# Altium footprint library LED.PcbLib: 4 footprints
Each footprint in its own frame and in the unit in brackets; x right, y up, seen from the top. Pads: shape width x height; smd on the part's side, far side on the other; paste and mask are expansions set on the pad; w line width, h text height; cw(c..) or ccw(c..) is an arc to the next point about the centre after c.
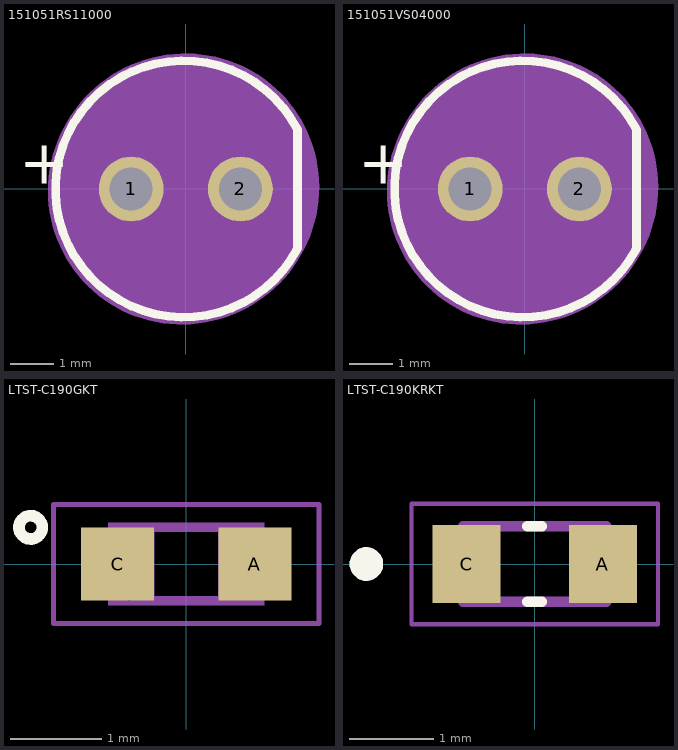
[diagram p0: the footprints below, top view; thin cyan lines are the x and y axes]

## 151051RS11000 [mm] "Red 645nm LED Indication - Discrete 2.1V Radial"
pads (2):
  round 1.508 hole 1: 1(-1.27,0) 2(1.27,0)
Top Overlay:
  lines w0.2: 2.589,-1.401 cw(c-0.047,0) 2.589,1.401 ; 2.6,-1.38 2.6,1.38
  text "+" at -3.88,0.118 h1.02
Mechanical 13:
  circle w0.1: c0,0 r2.5
  lines w0.1: 2.493,-1.452 cw(c-0.021,0) 2.493,1.452 ; 2.5,-1.44 2.5,1.44
  text "+" at -3.887,0.131 h1.02
Mechanical 15:
  region: 0.216,3.141 0.376,3.126 0.534,3.103 0.692,3.071 0.847,3.031 1,2.983 1.151,2.928 1.298,2.865 1.442,2.794 1.582,2.715 1.718,2.63 1.849,2.538 1.975,2.439 2.096,2.334 2.212,2.222 2.321,2.105 2.424,1.982 2.521,1.854 2.611,1.721 2.694,1.584 2.77,1.443 2.838,1.297 2.899,1.149 2.952,0.998 2.997,0.844 3.034,0.688 3.063,0.53 3.083,0.371 3.096,0.211 3.1,0.05 3.096,-0.116 3.083,-0.281 3.061,-0.445 3.032,-0.608 2.993,-0.77 2.947,-0.929 2.892,-1.085 2.829,-1.238 2.759,-1.388 2.681,-1.534 2.595,-1.676 2.502,-1.813 2.402,-1.945 2.295,-2.072 2.182,-2.193 2.063,-2.308 1.938,-2.417 1.808,-2.519 1.672,-2.615 1.532,-2.703 1.387,-2.784 1.239,-2.857 1.087,-2.922 0.931,-2.98 0.773,-3.029 0.613,-3.07 0.45,-3.103 0.286,-3.127 0.121,-3.143 -0.049,-3.15 -0.052,-3.15 -0.211,-3.148 -0.374,-3.138 -0.537,-3.119 -0.699,-3.092 -0.859,-3.056 -1.017,-3.012 -1.173,-2.959 -1.325,-2.898 -1.474,-2.83 -1.619,-2.753 -1.76,-2.669 -1.896,-2.577 -2.027,-2.479 -2.153,-2.374 -2.273,-2.262 -2.387,-2.144 -2.495,-2.02 -2.595,-1.89 -2.689,-1.756 -2.776,-1.616 -2.855,-1.473 -2.926,-1.325 -2.99,-1.174 -3.045,-1.019 -3.092,-0.862 -3.131,-0.703 -3.161,-0.541 -3.183,-0.379 -3.196,-0.215 -3.2,-0.051 -3.196,0.118 -3.182,0.287 -3.16,0.455 -3.129,0.621 -3.089,0.786 -3.04,0.948 -2.983,1.108 -2.917,1.264 -2.844,1.416 -2.762,1.565 -2.673,1.709 -2.576,1.848 -2.472,1.981 -2.361,2.109 -2.243,2.231 -2.119,2.347 -1.989,2.455 -1.854,2.557 -1.713,2.652 -1.568,2.739 -1.418,2.818 -1.264,2.889 -1.107,2.951 -0.946,3.006 -0.783,3.051 -0.618,3.089 -0.451,3.117 -0.283,3.136 -0.114,3.147 0.051,3.148
3D body "Download_STP_WL-TMRC-5mm+(rev1).stp": height 8.7, standoff -26.4, extent -2.954,-3.048 2.446,2.832

## 151051VS04000 [mm] "Green 572nm LED Indication - Discrete 2.1V Radial"
pads (2):
  round 1.508 hole 1: 1(-1.27,0) 2(1.27,0)
Top Overlay:
  lines w0.2: 2.589,-1.401 cw(c-0.047,0) 2.589,1.401 ; 2.6,-1.38 2.6,1.38
  text "+" at -3.88,0.118 h1.02
Mechanical 13:
  circle w0.1: c0,0 r2.5
  lines w0.1: 2.493,-1.452 cw(c-0.021,0) 2.493,1.452 ; 2.5,-1.44 2.5,1.44
  text "+" at -3.887,0.131 h1.02
Mechanical 15:
  region: 0.216,3.141 0.376,3.126 0.534,3.103 0.692,3.071 0.847,3.031 1,2.983 1.151,2.928 1.298,2.865 1.442,2.794 1.582,2.715 1.718,2.63 1.849,2.538 1.975,2.439 2.096,2.334 2.212,2.222 2.321,2.105 2.424,1.982 2.521,1.854 2.611,1.721 2.694,1.584 2.77,1.443 2.838,1.297 2.899,1.149 2.952,0.998 2.997,0.844 3.034,0.688 3.063,0.53 3.083,0.371 3.096,0.211 3.1,0.05 3.096,-0.116 3.083,-0.281 3.061,-0.445 3.032,-0.608 2.993,-0.77 2.947,-0.929 2.892,-1.085 2.829,-1.238 2.759,-1.388 2.681,-1.534 2.595,-1.676 2.502,-1.813 2.402,-1.945 2.295,-2.072 2.182,-2.193 2.063,-2.308 1.938,-2.417 1.808,-2.519 1.672,-2.615 1.532,-2.703 1.387,-2.784 1.239,-2.857 1.087,-2.922 0.931,-2.98 0.773,-3.029 0.613,-3.07 0.45,-3.103 0.286,-3.127 0.121,-3.143 -0.049,-3.15 -0.052,-3.15 -0.211,-3.148 -0.374,-3.138 -0.537,-3.119 -0.699,-3.092 -0.859,-3.056 -1.017,-3.012 -1.173,-2.959 -1.325,-2.898 -1.474,-2.83 -1.619,-2.753 -1.76,-2.669 -1.896,-2.577 -2.027,-2.479 -2.153,-2.374 -2.273,-2.262 -2.387,-2.144 -2.495,-2.02 -2.595,-1.89 -2.689,-1.756 -2.776,-1.616 -2.855,-1.473 -2.926,-1.325 -2.99,-1.174 -3.045,-1.019 -3.092,-0.862 -3.131,-0.703 -3.161,-0.541 -3.183,-0.379 -3.196,-0.215 -3.2,-0.051 -3.196,0.118 -3.182,0.287 -3.16,0.455 -3.129,0.621 -3.089,0.786 -3.04,0.948 -2.983,1.108 -2.917,1.264 -2.844,1.416 -2.762,1.565 -2.673,1.709 -2.576,1.848 -2.472,1.981 -2.361,2.109 -2.243,2.231 -2.119,2.347 -1.989,2.455 -1.854,2.557 -1.713,2.652 -1.568,2.739 -1.418,2.818 -1.264,2.889 -1.107,2.951 -0.946,3.006 -0.783,3.051 -0.618,3.089 -0.451,3.117 -0.283,3.136 -0.114,3.147 0.051,3.148
3D body "Download_STP_WL-TMRC-5mm+(rev1).stp": height 8.7, standoff -26.4, extent -2.954,-3.048 2.446,2.832

## LTST-C190GKT [mm] "Green 569nm LED Indication - Discrete 2.1V 0603 (1608 Metric)"
pads (2):
  rect 0.8x0.8 smd: A(0.75,0) C(-0.75,0)
Top Overlay:
  circle w0.127: c-1.7,0.4 r0.127
Mechanical 13:
  circle w0.051: c-0.625,-0.35 r0.075
  region: 0.65,0.175 0.55,0.175 0.55,0.275 0.65,0.275
  region: 0.65,-0.275 0.55,-0.275 0.55,-0.175 0.65,-0.175
  region: 0.575,-0.275 0.35,-0.275 0.35,0.275 0.575,0.275
  region: 0.85,0.25 0.35,0.25 0.35,0.45 0.85,0.45
  region: 0.851,-0.45 0.35,-0.45 0.35,-0.251 0.851,-0.251
  region: -0.351,-0.451 -0.576,-0.451 -0.576,0.451 -0.351,0.451
  region: -0.551,0.25 -0.85,0.25 -0.85,0.451 -0.551,0.451
  region: -0.35,-0.45 -0.725,-0.45 -0.725,-0.4 -0.35,-0.4
  region: -0.55,-0.276 -0.601,-0.276 -0.601,-0.225 -0.55,-0.225
  region: -0.7,-0.451 -0.851,-0.451 -0.851,-0.25 -0.7,-0.25
  lines w0.051: 0.825,-0.275 cw(c0.825,0) 0.825,0.275
  lines w0.102: -0.8,-0.3 ccw(c-0.826,0) -0.8,0.3 ; -0.375,-0.4 0.35,-0.4 ; -0.35,0.4 0.35,0.4
Mechanical 15:
  lines w0.05: -1.45,-0.65 -1.45,0.65 1.45,0.65 1.45,-0.65 -1.45,-0.65
3D body "LTST-C190GKT.STEP": height 0.8, standoff 0, extent -0.8,-0.4 0.8,0.4

## LTST-C190KRKT [mm] "Red 631nm LED Indication - Discrete 2V 0603 (1608 Metric)"
pads (2):
  rect 0.81x0.93 smd: A(0.81,0) C(-0.81,0)
Top Overlay:
  circle w0.2: c-2,0 r0.1
  lines w0.127: -0.085,-0.45 0.085,-0.45 ; -0.085,0.45 0.085,0.45
Mechanical 13:
  circle w0.2: c-2,0 r0.1
  lines w0.127: -0.85,-0.45 0.85,-0.45 0.85,0.45 -0.85,0.45 -0.85,-0.45
Mechanical 15:
  lines w0.05: -1.465,-0.715 1.465,-0.715 1.465,0.715 -1.465,0.715 -1.465,-0.715
3D body "step_temp.STEP": height 0.8, standoff 0, extent -0.8,-0.4 0.8,0.4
